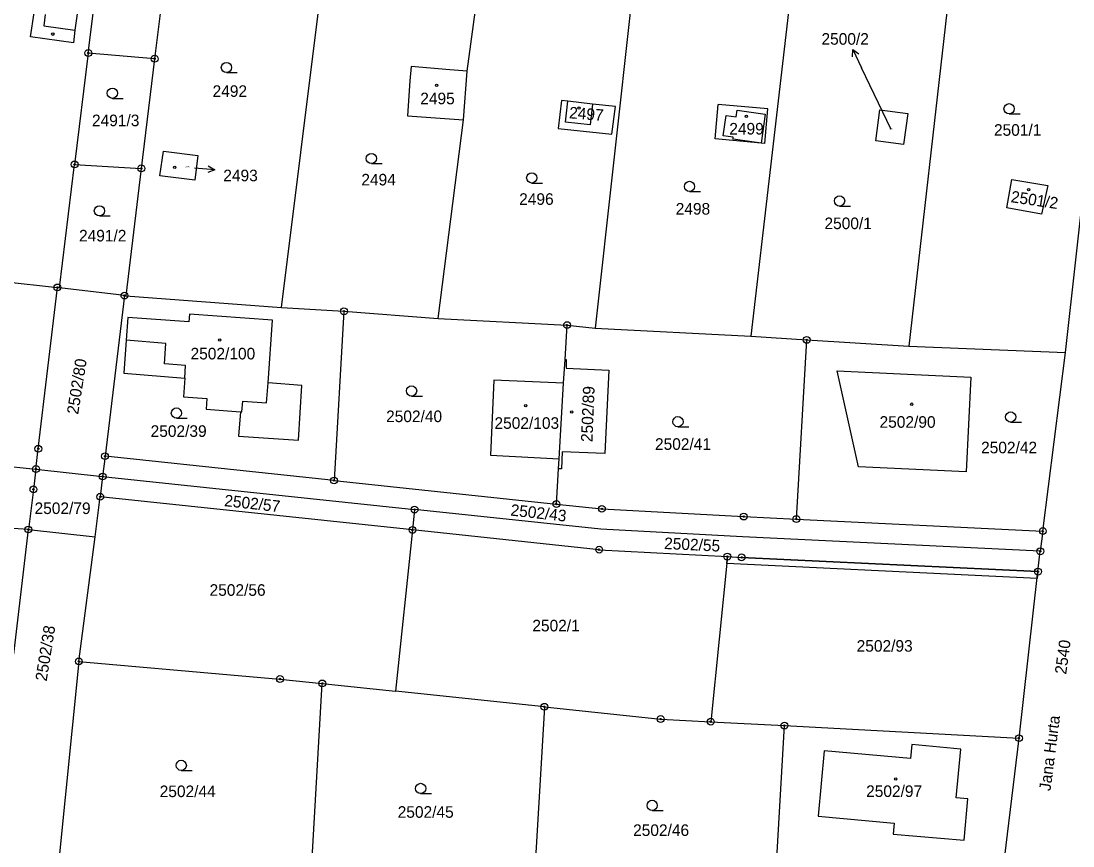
# Model space of a CAD drawing. Extents: x -755819 to -753140, y -1169796 to -1166000.
# Drawn here: x -754702.7 to -754548.4, y -1169070.4 to -1168949.3 of the extents above; entities that cross this region are included whole.
import ezdxf

# ---------------------------------------------------------------- set-up
doc = ezdxf.new("R2010")
doc.units = 0
for name, color, linetype in [('Vrstva 1', 7, 'Continuous'), ('Vrstva 15', 7, 'Continuous'), ('Vrstva 16', 7, 'Continuous'), ('Vrstva 18', 7, 'Continuous'), ('Vrstva 19', 7, 'Continuous'), ('Vrstva 24', 7, 'Continuous'), ('Vrstva 25', 7, 'Continuous'), ('Vrstva 27', 7, 'Continuous'), ('Vrstva 4', 7, 'Continuous'), ('Vrstva 6', 7, 'Continuous')]:
    doc.layers.add(name, color=color, linetype=linetype)

msp = doc.modelspace()

# ---------------------------------------------------------------- linework, layer by layer
at = {"layer": 'Vrstva 1'}
for p, q in [((-754692.83, -1168954.03), (-754689.59, -1168927.68)), ((-754679.94, -1168928.71), (-754683.1, -1168954.86)), ((-754664.49, -1168991.37), (-754657.04, -1168931.44)), ((-754637.28, -1168956.71), (-754634.16, -1168934.17)), ((-754612.06, -1168936.59), (-754618.5, -1168994.41)), ((-754589.1, -1168939.1), (-754595.65, -1168995.6)), ((-754693.43, -1168941.07), (-754694.81, -1168950.7)), ((-754566.16, -1168941.72), (-754572.49, -1168997.06)), ((-754549.49, -1168998), (-754543.55, -1168944.3)), ((-754701.29, -1168951.65), (-754700.79, -1168948.14)), ((-754695.01, -1168952.55), (-754701.29, -1168951.65)), ((-754694.81, -1168950.7), (-754695.01, -1168952.55)), ((-754692.83, -1168954.03), (-754694.84, -1168970.38)), ((-754683.1, -1168954.86), (-754692.83, -1168954.03)), ((-754683.1, -1168954.86), (-754685.06, -1168970.96)), ((-754645.49, -1168956.02), (-754645.66, -1168958.13)), ((-754639.81, -1168956.48), (-754645.49, -1168956.02)), ((-754637.28, -1168956.71), (-754639.81, -1168956.48)), ((-754637.8, -1168963.83), (-754637.28, -1168956.71)), ((-754645.66, -1168958.13), (-754646.02, -1168963.23)), ((-754618.89, -1168961.52), (-754622.5, -1168961.11)), ((-754577.31, -1168966.9), (-754576.75, -1168962.35)), ((-754576.75, -1168962.35), (-754572.6, -1168962.92)), ((-754646.02, -1168963.23), (-754637.8, -1168963.83)), ((-754641.49, -1168993.01), (-754637.8, -1168963.83)), ((-754572.6, -1168962.92), (-754573.25, -1168967.43)), ((-754573.25, -1168967.43), (-754577.31, -1168966.9)), ((-754682.33, -1168972.07), (-754681.82, -1168968.45)), ((-754681.82, -1168968.45), (-754676.75, -1168969.05)), ((-754676.75, -1168969.05), (-754677.21, -1168972.71)), ((-754697.07, -1168988.5), (-754694.84, -1168970.38)), ((-754694.84, -1168970.38), (-754685.06, -1168970.96)), ((-754685.06, -1168970.96), (-754687.32, -1168989.65)), ((-754677.21, -1168972.71), (-754682.33, -1168972.07)), ((-754558.08, -1168976.76), (-754557.39, -1168972.58)), ((-754557.39, -1168972.58), (-754552.07, -1168973.45)), ((-754552.07, -1168973.45), (-754553.03, -1168977.67)), ((-754553.03, -1168977.67), (-754558.08, -1168976.76)), ((-754705.32, -1168987.58), (-754697.37, -1168988.43)), ((-754700.16, -1169012.1), (-754697.37, -1168988.43)), ((-754697.37, -1168988.43), (-754697.07, -1168988.5)), ((-754687.53, -1168989.62), (-754697.07, -1168988.5)), ((-754687.53, -1168989.62), (-754690.37, -1169013.19)), ((-754687.53, -1168989.62), (-754687.32, -1168989.65)), ((-754687.32, -1168989.65), (-754664.49, -1168991.37)), ((-754664.49, -1168991.37), (-754655.33, -1168991.93)), ((-754687.05, -1168992.83), (-754687.29, -1168996.17)), ((-754678.08, -1168993.48), (-754687.05, -1168992.83)), ((-754678, -1168992.33), (-754678.08, -1168993.48)), ((-754665.79, -1168993.21), (-754678, -1168992.33)), ((-754666.46, -1169002.43), (-754665.79, -1168993.21)), ((-754655.33, -1168991.93), (-754656.78, -1169016.76)), ((-754655.33, -1168991.93), (-754641.49, -1168993.01)), ((-754641.49, -1168993.01), (-754622.6, -1168993.96)), ((-754622.9, -1168999.01), (-754622.6, -1168993.96)), ((-754622.6, -1168993.96), (-754618.5, -1168994.41)), ((-754618.5, -1168994.41), (-754595.65, -1168995.6)), ((-754687.29, -1168996.17), (-754687.6, -1169001.01)), ((-754595.65, -1168995.6), (-754587.46, -1168996.13)), ((-754588.97, -1169022.42), (-754587.46, -1168996.13)), ((-754587.46, -1168996.13), (-754572.49, -1168997.06)), ((-754572.49, -1168997.06), (-754549.49, -1168998)), ((-754552.82, -1169024.18), (-754549.49, -1168998)), ((-754623.11, -1169002.48), (-754622.9, -1168999.01)), ((-754622.9, -1168999.01), (-754622.72, -1168998.99)), ((-754622.72, -1168998.99), (-754622.72, -1169000.28)), ((-754687.6, -1169001.01), (-754678.69, -1169001.72)), ((-754622.72, -1169000.28), (-754616.47, -1169000.57)), ((-754616.47, -1169000.57), (-754617.06, -1169012.82)), ((-754582.98, -1169000.67), (-754563.36, -1169001.6)), ((-754579.87, -1169014.74), (-754582.98, -1169000.67)), ((-754678.69, -1169001.72), (-754678.88, -1169004.48)), ((-754661.49, -1169002.84), (-754666.46, -1169002.43)), ((-754633.33, -1169002.02), (-754633.82, -1169013.06)), ((-754623.11, -1169002.48), (-754633.33, -1169002.02)), ((-754623.76, -1169013.57), (-754623.11, -1169002.48)), ((-754563.36, -1169001.6), (-754564.06, -1169015.5)), ((-754662.02, -1169010.84), (-754661.49, -1169002.84)), ((-754678.88, -1169004.48), (-754675.43, -1169004.74)), ((-754675.43, -1169004.74), (-754675.54, -1169006.3)), ((-754675.54, -1169006.3), (-754670.52, -1169006.66)), ((-754670.52, -1169006.66), (-754670.8, -1169010.23)), ((-754758.37, -1169009.46), (-754700.51, -1169015.08)), ((-754670.8, -1169010.23), (-754662.02, -1169010.84)), ((-754700.51, -1169015.08), (-754700.16, -1169012.1)), ((-754690.37, -1169013.19), (-754690.73, -1169016.17)), ((-754656.78, -1169016.76), (-754690.37, -1169013.19)), ((-754633.82, -1169013.06), (-754623.76, -1169013.57)), ((-754623.32, -1169012.53), (-754623.44, -1169015.04)), ((-754617.06, -1169012.82), (-754623.32, -1169012.53)), ((-754623.85, -1169015.03), (-754623.76, -1169013.57)), ((-754564.06, -1169015.5), (-754579.87, -1169014.74)), ((-754700.51, -1169015.08), (-754700.88, -1169018.06)), ((-754690.73, -1169016.17), (-754691.08, -1169019.15)), ((-754690.73, -1169016.17), (-754644.97, -1169021.02)), ((-754624.16, -1169020.21), (-754623.85, -1169015.03)), ((-754623.44, -1169015.04), (-754623.85, -1169015.03)), ((-754700.88, -1169018.06), (-754701.62, -1169023.95)), ((-754656.78, -1169016.76), (-754624.16, -1169020.21)), ((-754691.84, -1169025.01), (-754691.08, -1169019.15)), ((-754645.28, -1169024.01), (-754691.08, -1169019.15)), ((-754644.97, -1169021.02), (-754645.28, -1169024.01)), ((-754617.66, -1169023.92), (-754644.97, -1169021.02)), ((-754624.16, -1169020.21), (-754617.5, -1169020.92)), ((-754617.5, -1169020.92), (-754596.7, -1169022.05)), ((-754596.7, -1169022.05), (-754588.97, -1169022.42)), ((-754588.97, -1169022.42), (-754552.82, -1169024.18)), ((-754701.62, -1169023.95), (-754709.58, -1169023.44)), ((-754703.77, -1169042.24), (-754701.62, -1169023.95)), ((-754645.28, -1169024.01), (-754647.79, -1169047.67)), ((-754617.9, -1169026.91), (-754645.28, -1169024.01)), ((-754596.86, -1169025.04), (-754617.66, -1169023.92)), ((-754552.82, -1169024.18), (-754553.19, -1169027.15)), ((-754694.22, -1169043.31), (-754691.84, -1169025.01)), ((-754553.19, -1169027.15), (-754596.86, -1169025.04)), ((-754617.9, -1169026.91), (-754599.09, -1169027.93)), ((-754553.54, -1169030.13), (-754553.19, -1169027.15)), ((-754599.09, -1169027.93), (-754601.53, -1169052.15)), ((-754599.09, -1169027.93), (-754597.01, -1169028.04)), ((-754553.54, -1169030.13), (-754597.01, -1169028.04)), ((-754556.31, -1169054.57), (-754553.54, -1169030.13)), ((-754694.22, -1169043.31), (-754697.19, -1169073)), ((-754694.22, -1169043.31), (-754664.72, -1169045.89)), ((-754664.72, -1169045.89), (-754658.51, -1169046.54)), ((-754660.22, -1169076.01), (-754658.51, -1169046.54)), ((-754658.51, -1169046.54), (-754647.79, -1169047.67)), ((-754625.93, -1169049.96), (-754647.79, -1169047.67)), ((-754625.93, -1169049.96), (-754627.64, -1169078.65)), ((-754625.93, -1169049.96), (-754608.87, -1169051.76)), ((-754608.87, -1169051.76), (-754601.53, -1169052.15)), ((-754601.53, -1169052.15), (-754590.72, -1169052.73)), ((-754592.37, -1169081.52), (-754590.72, -1169052.73)), ((-754590.72, -1169052.73), (-754556.31, -1169054.57)), ((-754559.86, -1169084.16), (-754556.31, -1169054.57)), ((-754584.91, -1169056.41), (-754585.79, -1169066)), ((-754572.22, -1169057.57), (-754584.91, -1169056.41)), ((-754572.04, -1169055.52), (-754572.22, -1169057.57)), ((-754564.87, -1169056.18), (-754572.04, -1169055.52)), ((-754565.51, -1169063.31), (-754564.87, -1169056.18)), ((-754563.84, -1169063.46), (-754565.51, -1169063.31)), ((-754564.38, -1169069.53), (-754563.84, -1169063.46)), ((-754585.79, -1169066), (-754574.61, -1169067.05)), ((-754574.61, -1169067.05), (-754574.76, -1169068.64)), ((-754574.76, -1169068.64), (-754564.38, -1169069.53))]:
    msp.add_line(p, q, dxfattribs=at)
at = {"layer": 'Vrstva 16'}
for p, q in [((-754580.7, -1168953.49), (-754579.4, -1168956.19)), ((-754575.05, -1168965.25), (-754579.4, -1168956.19)), ((-754674.27, -1168971.15), (-754677.26, -1168970.91))]:
    msp.add_line(p, q, dxfattribs=at)
for points in [[(-754580.72, -1168954.6), (-754580.7, -1168953.49), (-754579.82, -1168954.17)], [(-754675.23, -1168970.57), (-754674.27, -1168971.15), (-754675.31, -1168971.57)]]:
    msp.add_lwpolyline(points, dxfattribs=at)
at = {"layer": 'Vrstva 24'}
for centre, radius in [((-754692.83, -1168954.03), 0.5), ((-754692.83, -1168954.03), 0.1), ((-754683.1, -1168954.86), 0.5), ((-754683.1, -1168954.86), 0.1), ((-754694.84, -1168970.38), 0.5), ((-754694.84, -1168970.38), 0.1), ((-754685.06, -1168970.96), 0.5), ((-754685.06, -1168970.96), 0.1), ((-754697.37, -1168988.43), 0.5), ((-754697.37, -1168988.43), 0.1), ((-754687.53, -1168989.62), 0.5), ((-754687.53, -1168989.62), 0.1), ((-754655.33, -1168991.93), 0.5), ((-754655.33, -1168991.93), 0.1), ((-754622.6, -1168993.96), 0.5), ((-754622.6, -1168993.96), 0.1), ((-754587.46, -1168996.13), 0.5), ((-754587.46, -1168996.13), 0.1), ((-754700.16, -1169012.1), 0.5), ((-754700.16, -1169012.1), 0.1), ((-754690.37, -1169013.19), 0.5), ((-754690.37, -1169013.19), 0.1), ((-754700.51, -1169015.08), 0.5), ((-754700.51, -1169015.08), 0.1), ((-754690.73, -1169016.17), 0.5), ((-754690.73, -1169016.17), 0.1), ((-754656.78, -1169016.76), 0.5), ((-754700.88, -1169018.06), 0.5), ((-754700.88, -1169018.06), 0.1), ((-754656.78, -1169016.76), 0.1), ((-754691.08, -1169019.15), 0.5), ((-754691.08, -1169019.15), 0.1), ((-754644.97, -1169021.02), 0.5), ((-754644.97, -1169021.02), 0.1), ((-754624.16, -1169020.21), 0.5), ((-754624.16, -1169020.21), 0.1), ((-754617.5, -1169020.92), 0.5), ((-754617.5, -1169020.92), 0.1), ((-754596.7, -1169022.05), 0.5), ((-754596.7, -1169022.05), 0.1), ((-754588.97, -1169022.42), 0.5), ((-754588.97, -1169022.42), 0.1), ((-754701.62, -1169023.95), 0.5), ((-754701.62, -1169023.95), 0.1), ((-754645.28, -1169024.01), 0.5), ((-754645.28, -1169024.01), 0.1), ((-754552.82, -1169024.18), 0.5), ((-754552.82, -1169024.18), 0.1), ((-754617.9, -1169026.91), 0.5), ((-754617.9, -1169026.91), 0.1), ((-754553.19, -1169027.15), 0.5), ((-754553.19, -1169027.15), 0.1), ((-754599.09, -1169027.93), 0.5), ((-754599.09, -1169027.93), 0.1), ((-754597.01, -1169028.04), 0.5), ((-754597.01, -1169028.04), 0.1), ((-754553.54, -1169030.13), 0.5), ((-754553.54, -1169030.13), 0.1), ((-754694.22, -1169043.31), 0.5), ((-754694.22, -1169043.31), 0.1), ((-754664.72, -1169045.89), 0.5), ((-754664.72, -1169045.89), 0.1), ((-754658.51, -1169046.54), 0.5), ((-754658.51, -1169046.54), 0.1), ((-754625.93, -1169049.96), 0.5), ((-754625.93, -1169049.96), 0.1), ((-754608.87, -1169051.76), 0.5), ((-754608.87, -1169051.76), 0.1), ((-754601.53, -1169052.15), 0.5), ((-754601.53, -1169052.15), 0.1), ((-754590.72, -1169052.73), 0.5), ((-754590.72, -1169052.73), 0.1), ((-754556.31, -1169054.57), 0.5), ((-754556.31, -1169054.57), 0.1)]:
    msp.add_circle(centre, radius, dxfattribs=at)
at = {"layer": 'Vrstva 25'}
for p, q in [((-754672.57, -1168956.91), (-754670.97, -1168956.91)), ((-754689.3, -1168960.68), (-754687.7, -1168960.68)), ((-754557.77, -1168962.96), (-754556.17, -1168962.96)), ((-754651.31, -1168970.26), (-754649.71, -1168970.26)), ((-754627.79, -1168973.11), (-754626.19, -1168973.11)), ((-754604.64, -1168974.35), (-754603.04, -1168974.35)), ((-754691.2, -1168977.94), (-754689.6, -1168977.94)), ((-754582.63, -1168976.49), (-754581.03, -1168976.49)), ((-754645.41, -1169004.37), (-754643.81, -1169004.37)), ((-754679.91, -1169007.61), (-754678.31, -1169007.61)), ((-754557.54, -1169008.19), (-754555.94, -1169008.19)), ((-754606.34, -1169008.88), (-754604.74, -1169008.88)), ((-754679.19, -1169059.31), (-754677.59, -1169059.31)), ((-754644.08, -1169062.69), (-754642.48, -1169062.69)), ((-754610.12, -1169065.18), (-754608.52, -1169065.18))]:
    msp.add_line(p, q, dxfattribs=at)
for centre, radius in [((-754698.03, -1168951.26), 0.175), ((-754672.57, -1168956.16), 0.75), ((-754689.3, -1168959.93), 0.75), ((-754641.74, -1168958.77), 0.175), ((-754620.85, -1168962.11), 0.175), ((-754557.77, -1168962.21), 0.75), ((-754596.3, -1168963.31), 0.175), ((-754651.31, -1168969.51), 0.75), ((-754680.16, -1168970.79), 0.175), ((-754627.79, -1168972.36), 0.75), ((-754604.64, -1168973.6), 0.75), ((-754554.91, -1168974.09), 0.175), ((-754582.63, -1168975.74), 0.75), ((-754691.2, -1168977.19), 0.75), ((-754673.56, -1168996.16), 0.175), ((-754645.41, -1169003.62), 0.75), ((-754628.66, -1169005.78), 0.175), ((-754572.06, -1169005.56), 0.175), ((-754679.91, -1169006.86), 0.75), ((-754621.93, -1169006.69), 0.175), ((-754557.54, -1169007.44), 0.75), ((-754606.34, -1169008.13), 0.75), ((-754679.19, -1169058.56), 0.75), ((-754644.08, -1169061.94), 0.75), ((-754574.39, -1169060.56), 0.175), ((-754610.12, -1169064.43), 0.75)]:
    msp.add_circle(centre, radius, dxfattribs=at)
at = {"layer": 'Vrstva 27'}
for p, q in [((-754599.19, -1169028.93), (-754599.09, -1169027.93)), ((-754599.09, -1169027.93), (-754597.01, -1169028.04)), ((-754597.01, -1169028.04), (-754553.54, -1169030.13)), ((-754553.65, -1169031.12), (-754599.19, -1169028.93)), ((-754553.54, -1169030.13), (-754553.65, -1169031.12))]:
    msp.add_line(p, q, dxfattribs=at)
at = {"layer": 'Vrstva 4'}
for p, q in [((-754699.17, -1168948.37), (-754699.37, -1168950.05)), ((-754699.37, -1168950.05), (-754694.81, -1168950.7)), ((-754623.44, -1168961), (-754623.9, -1168965.09)), ((-754622.5, -1168961.11), (-754623.44, -1168961)), ((-754615.52, -1168961.9), (-754618.89, -1168961.52)), ((-754616.02, -1168965.96), (-754615.52, -1168961.9)), ((-754600.89, -1168966.61), (-754600.43, -1168961.58)), ((-754593.16, -1168962.22), (-754600.43, -1168961.58)), ((-754593.61, -1168967.3), (-754593.16, -1168962.22)), ((-754623.9, -1168965.09), (-754616.02, -1168965.96)), ((-754594.15, -1168967.25), (-754600.89, -1168966.61)), ((-754593.61, -1168967.3), (-754594.15, -1168967.25)), ((-754681.45, -1168996.68), (-754687.29, -1168996.17)), ((-754681.64, -1168999.63), (-754681.45, -1168996.68)), ((-754678.56, -1168999.87), (-754681.64, -1168999.63)), ((-754678.69, -1169001.72), (-754678.56, -1168999.87)), ((-754666.67, -1169005.37), (-754666.46, -1169002.43)), ((-754670.29, -1169006.67), (-754670.17, -1169005.13)), ((-754670.17, -1169005.13), (-754666.67, -1169005.37)), ((-754670.52, -1169006.66), (-754670.29, -1169006.67))]:
    msp.add_line(p, q, dxfattribs=at)
at = {"layer": 'Vrstva 6'}
for p, q in [((-754622.84, -1168964.18), (-754622.5, -1168961.11)), ((-754618.89, -1168961.52), (-754619.23, -1168964.58)), ((-754597.8, -1168963.4), (-754597.65, -1168962.41)), ((-754597.65, -1168962.41), (-754593.55, -1168962.99)), ((-754599.7, -1168966.16), (-754599.28, -1168963.19)), ((-754599.28, -1168963.19), (-754597.8, -1168963.4)), ((-754593.55, -1168962.99), (-754594.15, -1168967.25)), ((-754619.23, -1168964.58), (-754622.84, -1168964.18)), ((-754598.22, -1168966.37), (-754599.7, -1168966.16)), ((-754598.26, -1168966.67), (-754598.22, -1168966.37)), ((-754594.15, -1168967.25), (-754598.26, -1168966.67)), ((-754700.51, -1169015.08), (-754690.73, -1169016.17)), ((-754701.62, -1169023.95), (-754691.84, -1169025.01))]:
    msp.add_line(p, q, dxfattribs=at)

# ---------------------------------------------------------------- texts
at = {"layer": 'Vrstva 15'}
msp.add_text('Jana Hurta', height=1.7, rotation=82.6778, dxfattribs=at).set_placement((-754551.7, -1169062.38))
at = {"layer": 'Vrstva 16'}
for s, p in [('2500/2', (-754585.29, -1168952.81)), ('2493', (-754673.03, -1168972.85))]:
    msp.add_text(s, height=1.7, dxfattribs=at).set_placement(p)
at = {"layer": 'Vrstva 18'}
for s, height, p in [('2492', 1.7, (-754674.6, -1168960.47)), ('2491/3', 1.7, (-754692.29, -1168964.77)), ('2500/2', 0.1, (-754575.31, -1168965.25)), ('2501/1', 1.7, (-754559.99, -1168966.17)), ('2494', 1.7, (-754652.78, -1168973.46)), ('2496', 1.7, (-754629.63, -1168976.31)), ('2498', 1.7, (-754606.67, -1168977.74)), ('2500/1', 1.7, (-754584.85, -1168979.87)), ('2491/2', 1.7, (-754694.19, -1168981.68)), ('2502/40', 1.7, (-754649.15, -1169008.19)), ('2502/39', 1.7, (-754683.69, -1169010.36)), ('2502/41', 1.7, (-754609.71, -1169012.26)), ('2502/42', 1.7, (-754561.88, -1169012.77)), ('2502/79', 1.7, (-754700.71, -1169021.68)), ('2502/56', 1.7, (-754675.04, -1169033.68)), ('2502/1', 1.7, (-754627.7, -1169038.9)), ('2502/93', 1.7, (-754580.13, -1169041.88)), ('2502/44', 1.7, (-754682.36, -1169063.22)), ('2502/45', 1.7, (-754647.45, -1169066.25)), ('2502/46', 1.7, (-754612.92, -1169068.92))]:
    msp.add_text(s, height=height, dxfattribs=at).set_placement(p)
for s, rotation, p in [('2502/80', 81.0162, (-754694.32, -1169007.14)), ('2502/57', 353.6868, (-754672.95, -1169020.51)), ('2502/43', 353.6868, (-754630.96, -1169021.9)), ('2502/55', 357.2965, (-754608.4, -1169026.81)), ('2502/38', 81.0162, (-754698.94, -1169046.29)), ('2540', 82.2767, (-754549.4, -1169045.28))]:
    msp.add_text(s, height=1.7, rotation=rotation, dxfattribs=at).set_placement(p)
at = {"layer": 'Vrstva 19'}
for s, height, p in [('2495', 1.7, (-754644.14, -1168961.55)), ('2499', 1.7, (-754598.81, -1168965.99)), ('2493', 0.2, (-754678.61, -1168970.79)), ('2502/100', 1.7, (-754677.83, -1168998.99)), ('2502/90', 1.7, (-754576.77, -1169009.02)), ('2502/103', 1.7, (-754633.25, -1169009.18)), ('2502/97', 1.7, (-754578.74, -1169063.2))]:
    msp.add_text(s, height=height, dxfattribs=at).set_placement(p)
for s, rotation, p in [('2497', 355.2911, (-754622.36, -1168963.6)), ('2501/2', 351.5669, (-754557.59, -1168975.91)), ('2502/89', 87.7198, (-754618.88, -1169011.15))]:
    msp.add_text(s, height=1.7, rotation=rotation, dxfattribs=at).set_placement(p)

doc.saveas('drawing.dxf')
